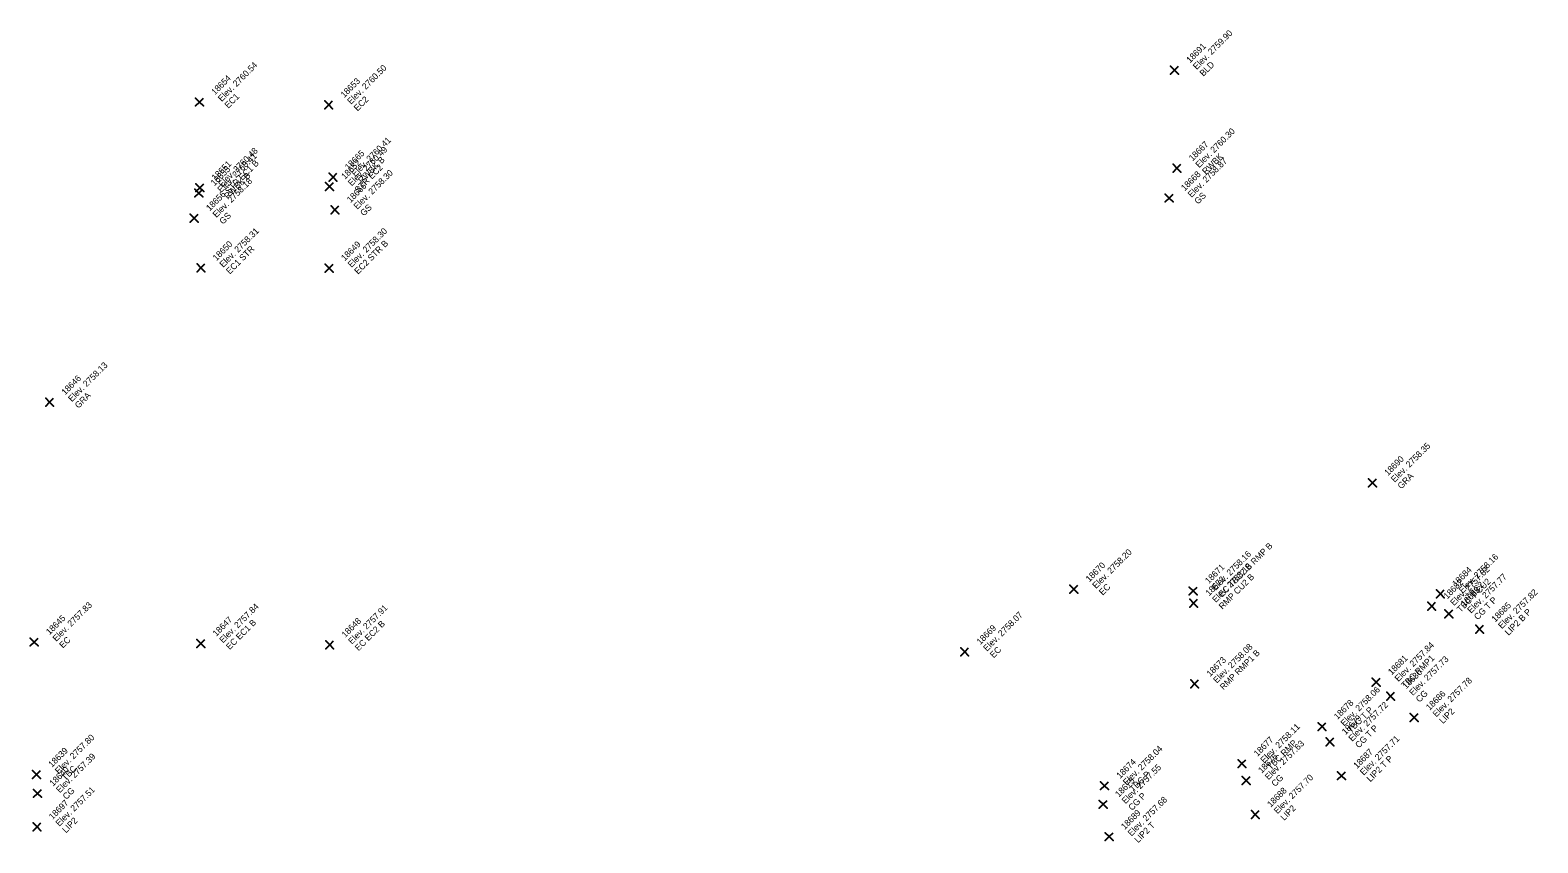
# Model space of a CAD drawing. Extents: x 2493999 to 2503109, y 700767 to 706646.
# Drawn here: x 2502361.8 to 2502419.4, y 700894.7 to 700925.7 of the extents above; entities that cross this region are included whole.
import ezdxf

# ---------------------------------------------------------------- set-up
doc = ezdxf.new("R2010")
doc.units = 0
doc.layers.add('ALG_CL_BLUE_Horiz', color=7, linetype='Continuous')
doc.layers.add('DES_SURFACE_Existing-Ground', color=7, linetype='Continuous')

msp = doc.modelspace()

# ---------------------------------------------------------------- linework, layer by layer
at = {"layer": 'ALG_CL_BLUE_Horiz'}
for points in [[(2502405.506, 700924.19), (2502405.356, 700924.34), (2502405.506, 700924.19), (2502405.356, 700924.04), (2502405.506, 700924.19), (2502405.656, 700924.04), (2502405.506, 700924.19), (2502405.656, 700924.34)], [(2502368.257, 700922.971), (2502368.107, 700923.121), (2502368.257, 700922.971), (2502368.107, 700922.821), (2502368.257, 700922.971), (2502368.407, 700922.821), (2502368.257, 700922.971), (2502368.407, 700923.121)], [(2502373.195, 700922.863), (2502373.045, 700923.013), (2502373.195, 700922.863), (2502373.045, 700922.713), (2502373.195, 700922.863), (2502373.345, 700922.713), (2502373.195, 700922.863), (2502373.345, 700923.013)], [(2502373.36, 700920.104), (2502373.21, 700920.254), (2502373.36, 700920.104), (2502373.21, 700919.954), (2502373.36, 700920.104), (2502373.51, 700919.954), (2502373.36, 700920.104), (2502373.51, 700920.254)], [(2502405.6, 700920.445), (2502405.45, 700920.595), (2502405.6, 700920.445), (2502405.45, 700920.295), (2502405.6, 700920.445), (2502405.75, 700920.295), (2502405.6, 700920.445), (2502405.75, 700920.595)], [(2502368.236, 700919.497), (2502368.086, 700919.647), (2502368.236, 700919.497), (2502368.086, 700919.347), (2502368.236, 700919.497), (2502368.386, 700919.347), (2502368.236, 700919.497), (2502368.386, 700919.647)], [(2502368.274, 700919.699), (2502368.124, 700919.849), (2502368.274, 700919.699), (2502368.124, 700919.549), (2502368.274, 700919.699), (2502368.424, 700919.549), (2502368.274, 700919.699), (2502368.424, 700919.849)], [(2502373.223, 700919.744), (2502373.073, 700919.894), (2502373.223, 700919.744), (2502373.073, 700919.594), (2502373.223, 700919.744), (2502373.373, 700919.594), (2502373.223, 700919.744), (2502373.373, 700919.894)], [(2502405.302, 700919.306), (2502405.152, 700919.456), (2502405.302, 700919.306), (2502405.152, 700919.156), (2502405.302, 700919.306), (2502405.452, 700919.156), (2502405.302, 700919.306), (2502405.452, 700919.456)], [(2502373.436, 700918.854), (2502373.286, 700919.004), (2502373.436, 700918.854), (2502373.286, 700918.704), (2502373.436, 700918.854), (2502373.586, 700918.704), (2502373.436, 700918.854), (2502373.586, 700919.004)], [(2502368.058, 700918.539), (2502367.908, 700918.689), (2502368.058, 700918.539), (2502367.908, 700918.389), (2502368.058, 700918.539), (2502368.208, 700918.389), (2502368.058, 700918.539), (2502368.208, 700918.689)], [(2502368.315, 700916.638), (2502368.165, 700916.788), (2502368.315, 700916.638), (2502368.165, 700916.488), (2502368.315, 700916.638), (2502368.465, 700916.488), (2502368.315, 700916.638), (2502368.465, 700916.788)], [(2502373.216, 700916.631), (2502373.066, 700916.781), (2502373.216, 700916.631), (2502373.066, 700916.481), (2502373.216, 700916.631), (2502373.366, 700916.481), (2502373.216, 700916.631), (2502373.366, 700916.781)], [(2502362.534, 700911.511), (2502362.384, 700911.661), (2502362.534, 700911.511), (2502362.384, 700911.361), (2502362.534, 700911.511), (2502362.684, 700911.361), (2502362.534, 700911.511), (2502362.684, 700911.661)], [(2502413.066, 700908.431), (2502412.916, 700908.581), (2502413.066, 700908.431), (2502412.916, 700908.281), (2502413.066, 700908.431), (2502413.216, 700908.281), (2502413.066, 700908.431), (2502413.216, 700908.581)], [(2502401.661, 700904.374), (2502401.511, 700904.524), (2502401.661, 700904.374), (2502401.511, 700904.224), (2502401.661, 700904.374), (2502401.811, 700904.224), (2502401.661, 700904.374), (2502401.811, 700904.524)], [(2502406.218, 700904.303), (2502406.068, 700904.453), (2502406.218, 700904.303), (2502406.068, 700904.153), (2502406.218, 700904.303), (2502406.368, 700904.153), (2502406.218, 700904.303), (2502406.368, 700904.453)], [(2502406.235, 700903.838), (2502406.085, 700903.988), (2502406.235, 700903.838), (2502406.085, 700903.688), (2502406.235, 700903.838), (2502406.385, 700903.688), (2502406.235, 700903.838), (2502406.385, 700903.988)], [(2502415.661, 700904.196), (2502415.511, 700904.346), (2502415.661, 700904.196), (2502415.511, 700904.046), (2502415.661, 700904.196), (2502415.811, 700904.046), (2502415.661, 700904.196), (2502415.811, 700904.346)], [(2502415.33, 700903.724), (2502415.18, 700903.874), (2502415.33, 700903.724), (2502415.18, 700903.574), (2502415.33, 700903.724), (2502415.48, 700903.574), (2502415.33, 700903.724), (2502415.48, 700903.874)], [(2502415.984, 700903.433), (2502415.834, 700903.583), (2502415.984, 700903.433), (2502415.834, 700903.283), (2502415.984, 700903.433), (2502416.134, 700903.283), (2502415.984, 700903.433), (2502416.134, 700903.583)], [(2502417.16, 700902.843), (2502417.01, 700902.993), (2502417.16, 700902.843), (2502417.01, 700902.693), (2502417.16, 700902.843), (2502417.31, 700902.693), (2502417.16, 700902.843), (2502417.31, 700902.993)], [(2502361.941, 700902.354), (2502361.791, 700902.504), (2502361.941, 700902.354), (2502361.791, 700902.204), (2502361.941, 700902.354), (2502362.091, 700902.204), (2502361.941, 700902.354), (2502362.091, 700902.504)], [(2502368.311, 700902.295), (2502368.161, 700902.445), (2502368.311, 700902.295), (2502368.161, 700902.145), (2502368.311, 700902.295), (2502368.461, 700902.145), (2502368.311, 700902.295), (2502368.461, 700902.445)], [(2502373.233, 700902.249), (2502373.083, 700902.399), (2502373.233, 700902.249), (2502373.083, 700902.099), (2502373.233, 700902.249), (2502373.383, 700902.099), (2502373.233, 700902.249), (2502373.383, 700902.399)], [(2502397.49, 700901.98), (2502397.34, 700902.13), (2502397.49, 700901.98), (2502397.34, 700901.83), (2502397.49, 700901.98), (2502397.64, 700901.83), (2502397.49, 700901.98), (2502397.64, 700902.13)], [(2502406.274, 700900.759), (2502406.124, 700900.909), (2502406.274, 700900.759), (2502406.124, 700900.609), (2502406.274, 700900.759), (2502406.424, 700900.609), (2502406.274, 700900.759), (2502406.424, 700900.909)], [(2502413.209, 700900.823), (2502413.059, 700900.973), (2502413.209, 700900.823), (2502413.059, 700900.673), (2502413.209, 700900.823), (2502413.359, 700900.673), (2502413.209, 700900.823), (2502413.359, 700900.973)], [(2502413.761, 700900.287), (2502413.611, 700900.437), (2502413.761, 700900.287), (2502413.611, 700900.137), (2502413.761, 700900.287), (2502413.911, 700900.137), (2502413.761, 700900.287), (2502413.911, 700900.437)], [(2502414.658, 700899.469), (2502414.508, 700899.619), (2502414.658, 700899.469), (2502414.508, 700899.319), (2502414.658, 700899.469), (2502414.808, 700899.319), (2502414.658, 700899.469), (2502414.808, 700899.619)], [(2502411.141, 700899.122), (2502410.991, 700899.272), (2502411.141, 700899.122), (2502410.991, 700898.972), (2502411.141, 700899.122), (2502411.291, 700898.972), (2502411.141, 700899.122), (2502411.291, 700899.272)], [(2502411.444, 700898.54), (2502411.294, 700898.69), (2502411.444, 700898.54), (2502411.294, 700898.39), (2502411.444, 700898.54), (2502411.594, 700898.39), (2502411.444, 700898.54), (2502411.594, 700898.69)], [(2502408.082, 700897.711), (2502407.932, 700897.861), (2502408.082, 700897.711), (2502407.932, 700897.561), (2502408.082, 700897.711), (2502408.232, 700897.561), (2502408.082, 700897.711), (2502408.232, 700897.861)], [(2502362.033, 700897.297), (2502361.883, 700897.447), (2502362.033, 700897.297), (2502361.883, 700897.147), (2502362.033, 700897.297), (2502362.183, 700897.147), (2502362.033, 700897.297), (2502362.183, 700897.447)], [(2502402.832, 700896.866), (2502402.682, 700897.016), (2502402.832, 700896.866), (2502402.682, 700896.716), (2502402.832, 700896.866), (2502402.982, 700896.716), (2502402.832, 700896.866), (2502402.982, 700897.016)], [(2502408.246, 700897.068), (2502408.096, 700897.218), (2502408.246, 700897.068), (2502408.096, 700896.918), (2502408.246, 700897.068), (2502408.396, 700896.918), (2502408.246, 700897.068), (2502408.396, 700897.218)], [(2502411.883, 700897.249), (2502411.733, 700897.399), (2502411.883, 700897.249), (2502411.733, 700897.099), (2502411.883, 700897.249), (2502412.033, 700897.099), (2502411.883, 700897.249), (2502412.033, 700897.399)], [(2502362.073, 700896.574), (2502361.923, 700896.724), (2502362.073, 700896.574), (2502361.923, 700896.424), (2502362.073, 700896.574), (2502362.223, 700896.424), (2502362.073, 700896.574), (2502362.223, 700896.724)], [(2502402.782, 700896.156), (2502402.632, 700896.306), (2502402.782, 700896.156), (2502402.632, 700896.006), (2502402.782, 700896.156), (2502402.932, 700896.006), (2502402.782, 700896.156), (2502402.932, 700896.306)], [(2502408.591, 700895.771), (2502408.441, 700895.921), (2502408.591, 700895.771), (2502408.441, 700895.621), (2502408.591, 700895.771), (2502408.741, 700895.621), (2502408.591, 700895.771), (2502408.741, 700895.921)], [(2502362.054, 700895.3), (2502361.904, 700895.45), (2502362.054, 700895.3), (2502361.904, 700895.15), (2502362.054, 700895.3), (2502362.204, 700895.15), (2502362.054, 700895.3), (2502362.204, 700895.45)], [(2502403.01, 700894.922), (2502402.86, 700895.072), (2502403.01, 700894.922), (2502402.86, 700894.772), (2502403.01, 700894.922), (2502403.16, 700894.772), (2502403.01, 700894.922), (2502403.16, 700895.072)]]:
    msp.add_lwpolyline(points, dxfattribs=at)

# ---------------------------------------------------------------- texts
at = {"layer": 'DES_SURFACE_Existing-Ground'}
for s, p in [('Elev. 2759.90', (2502406.355, 700924.19)), ('18691', (2502406.1, 700924.445)), ('Elev. 2760.54', (2502369.106, 700922.971)), ('Elev. 2760.50', (2502374.044, 700922.863)), ('BLD', (2502406.609, 700923.935)), ('18654', (2502368.851, 700923.226)), ('18653', (2502373.789, 700923.118)), ('EC1', (2502369.36, 700922.716)), ('EC2', (2502374.298, 700922.608)), ('Elev. 2760.30', (2502406.449, 700920.445)), ('Elev. 2760.48', (2502369.123, 700919.699)), ('Elev. 2760.49', (2502374.072, 700919.744)), ('Elev. 2760.41', (2502374.209, 700920.104)), ('18667', (2502406.194, 700920.7)), ('18651', (2502368.868, 700919.954)), ('Elev. 2760.41', (2502369.085, 700919.497)), ('STR EC1 B', (2502369.377, 700919.444)), ('18652', (2502373.817, 700919.999)), ('18665', (2502373.954, 700920.359)), ('RWBK B', (2502374.463, 700919.849)), ('Elev. 2758.87', (2502406.151, 700919.306)), ('RWBK', (2502406.703, 700920.19)), ('18655', (2502368.83, 700919.752)), ('Elev. 2758.18', (2502368.907, 700918.539)), ('RWBK B', (2502369.339, 700919.242)), ('Elev. 2758.30', (2502374.285, 700918.854)), ('STR EC2', (2502374.326, 700919.489)), ('18668', (2502405.896, 700919.561)), ('18656', (2502368.652, 700918.794)), ('18666', (2502374.03, 700919.109)), ('GS', (2502406.405, 700919.051)), ('GS', (2502374.539, 700918.599)), ('GS', (2502369.161, 700918.284)), ('Elev. 2758.31', (2502369.164, 700916.638)), ('Elev. 2758.30', (2502374.065, 700916.631)), ('18650', (2502368.909, 700916.893)), ('EC1 STR', (2502369.418, 700916.383)), ('18649', (2502373.81, 700916.886)), ('EC2 STR B', (2502374.319, 700916.376)), ('18646', (2502363.128, 700911.766)), ('Elev. 2758.13', (2502363.383, 700911.511)), ('GRA', (2502363.637, 700911.256)), ('Elev. 2758.35', (2502413.915, 700908.431)), ('18690', (2502413.66, 700908.686)), ('GRA', (2502414.169, 700908.176)), ('Elev. 2758.20', (2502402.51, 700904.374)), ('Elev. 2758.16', (2502407.067, 700904.303)), ('EC TBC2 B RMP B', (2502407.321, 700904.048)), ('Elev. 2758.16', (2502416.51, 700904.196)), ('18670', (2502402.255, 700904.629)), ('18671', (2502406.812, 700904.558)), ('Elev. 2758.18', (2502407.084, 700903.838)), ('Elev. 2757.82', (2502416.179, 700903.724)), ('18684', (2502416.255, 700904.451)), ('EC', (2502402.764, 700904.119)), ('18672', (2502406.829, 700904.093)), ('RMP CU2 B', (2502407.338, 700903.583)), ('18682', (2502415.924, 700903.979)), ('TBC T CU2', (2502416.433, 700903.469)), ('TBC2', (2502416.764, 700903.941)), ('Elev. 2757.77', (2502416.833, 700903.433)), ('18683', (2502416.578, 700903.688)), ('CG T P', (2502417.087, 700903.178)), ('Elev. 2757.82', (2502418.009, 700902.843)), ('18645', (2502362.535, 700902.609)), ('Elev. 2757.83', (2502362.79, 700902.354)), ('18647', (2502368.905, 700902.55)), ('Elev. 2757.84', (2502369.16, 700902.295)), ('Elev. 2757.91', (2502374.082, 700902.249)), ('Elev. 2758.07', (2502398.339, 700901.98)), ('18685', (2502417.754, 700903.098)), ('LIP2 B P', (2502418.263, 700902.588)), ('EC EC1 B', (2502369.414, 700902.04)), ('18648', (2502373.827, 700902.504)), ('EC EC2 B', (2502374.336, 700901.994)), ('18669', (2502398.084, 700902.235)), ('EC', (2502363.044, 700902.099)), ('EC', (2502398.593, 700901.725)), ('Elev. 2758.08', (2502407.123, 700900.759)), ('Elev. 2757.84', (2502414.058, 700900.823)), ('18673', (2502406.868, 700901.014)), ('RMP RMP1 B', (2502407.377, 700900.504)), ('18681', (2502413.803, 700901.078)), ('TBC RMP1', (2502414.312, 700900.568)), ('Elev. 2757.73', (2502414.61, 700900.287)), ('18680', (2502414.355, 700900.542)), ('Elev. 2758.06', (2502411.99, 700899.122)), ('CG', (2502414.864, 700900.032)), ('18686', (2502415.252, 700899.724)), ('Elev. 2757.78', (2502415.507, 700899.469)), ('18678', (2502411.735, 700899.377)), ('Elev. 2757.72', (2502412.293, 700898.54)), ('18679', (2502412.038, 700898.795)), ('TBC T P', (2502412.244, 700898.867)), ('LIP2', (2502415.761, 700899.214)), ('Elev. 2757.80', (2502362.882, 700897.297)), ('18677', (2502408.676, 700897.966)), ('Elev. 2758.11', (2502408.931, 700897.711)), ('CG T P', (2502412.547, 700898.285)), ('Elev. 2757.71', (2502412.732, 700897.249)), ('18639', (2502362.627, 700897.552)), ('Elev. 2758.04', (2502403.681, 700896.866)), ('Elev. 2757.63', (2502409.095, 700897.068)), ('TBC RMP', (2502409.185, 700897.456)), ('18687', (2502412.477, 700897.504)), ('18640', (2502362.667, 700896.829)), ('Elev. 2757.39', (2502362.922, 700896.574)), ('TBC', (2502363.136, 700897.042)), ('18674', (2502403.426, 700897.121)), ('Elev. 2757.55', (2502403.631, 700896.156)), ('18676', (2502408.84, 700897.323)), ('LIP2 T P', (2502412.986, 700896.994)), ('18675', (2502403.376, 700896.411)), ('TBC P', (2502403.935, 700896.611)), ('CG', (2502409.349, 700896.813)), ('Elev. 2757.70', (2502409.44, 700895.771)), ('Elev. 2757.51', (2502362.903, 700895.3)), ('CG', (2502363.176, 700896.319)), ('Elev. 2757.68', (2502403.859, 700894.922)), ('CG P', (2502403.885, 700895.901)), ('18688', (2502409.185, 700896.026)), ('18697', (2502362.648, 700895.555)), ('18689', (2502403.604, 700895.177)), ('LIP2', (2502409.694, 700895.516)), ('LIP2', (2502363.157, 700895.045)), ('LIP2 T', (2502404.113, 700894.667))]:
    msp.add_text(s, height=0.24, rotation=45, dxfattribs=at).set_placement(p)

doc.saveas('drawing.dxf')
